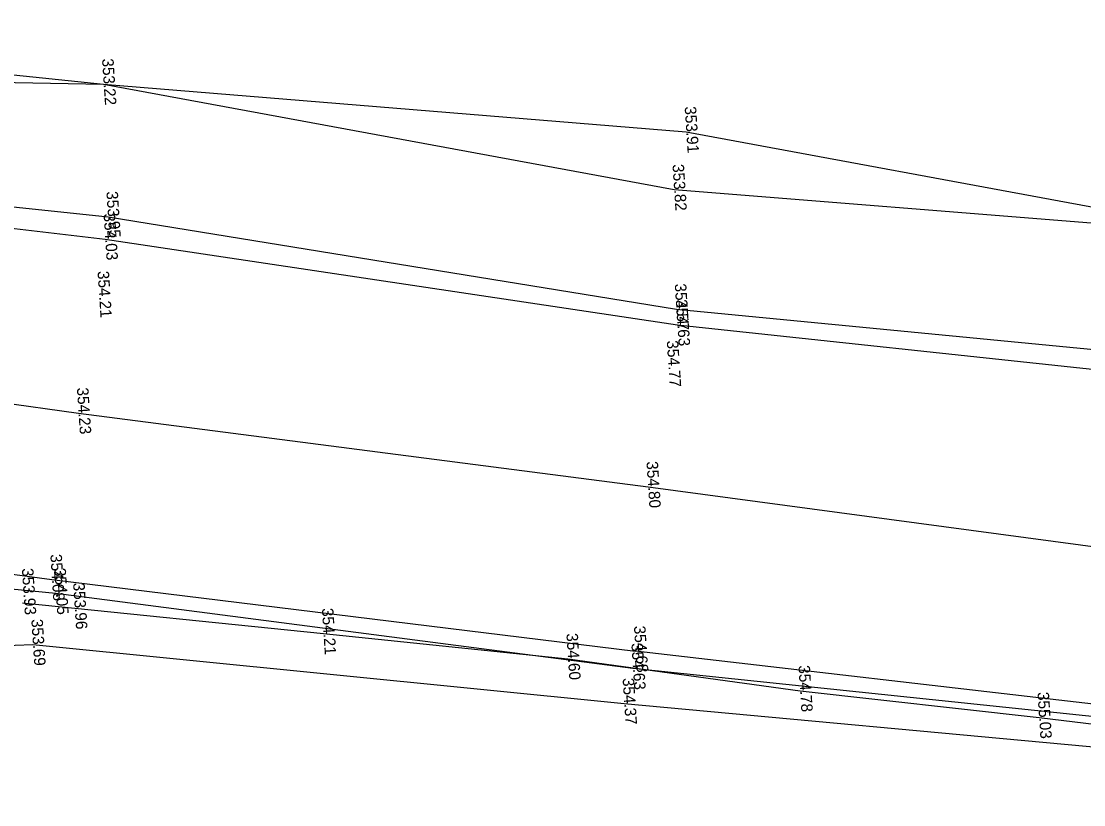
# Model space of a CAD drawing. Extents: x -600096 to -597522, y -1151695 to -1149849.
# Drawn here: x -599588.39 to -599571.03, y -1151436.31 to -1151423.5 of the extents above; entities that cross this region are included whole.
import ezdxf

# ---------------------------------------------------------------- set-up
doc = ezdxf.new("R2010")
doc.units = 0
for name, color, linetype in [('Hrana komunikace', 7, 'Continuous'), ('MPPV_Dno_prikopu', 7, 'Continuous'), ('MPPV_komunikace', 7, 'Continuous'), ('MPPV_svah', 7, 'Continuous'), ('MPPV_vodorovne_znaceni', 7, 'Continuous'), ('Svodidla', 7, 'Continuous'), ('Vrstva 12', 7, 'Continuous')]:
    doc.layers.add(name, color=color, linetype=linetype)

msp = doc.modelspace()

# ---------------------------------------------------------------- linework, layer by layer
at = {"layer": 'Hrana komunikace'}
for p, q in [((-599597.086, -1151425.633), (-599586.975, -1151426.697)), ((-599586.975, -1151426.697), (-599577.687, -1151428.205)), ((-599577.687, -1151428.205), (-599568.056, -1151429.139)), ((-599587.826, -1151432.855), (-599598.052, -1151431.869)), ((-599578.396, -1151434.083), (-599587.826, -1151432.855)), ((-599568.951, -1151435.07), (-599578.396, -1151434.083))]:
    msp.add_line(p, q, dxfattribs=at)
at = {"layer": 'MPPV_Dno_prikopu'}
for p, q in [((-599597.189, -1151424.357), (-599587.047, -1151424.527)), ((-599587.047, -1151424.527), (-599577.724, -1151426.253)), ((-599577.724, -1151426.253), (-599568.437, -1151426.99))]:
    msp.add_line(p, q, dxfattribs=at)
at = {"layer": 'MPPV_komunikace'}
for p, q in [((-599597.19, -1151425.88), (-599587.021, -1151427.06)), ((-599587.021, -1151427.06), (-599577.67, -1151428.464)), ((-599577.67, -1151428.464), (-599568.103, -1151429.483)), ((-599597.941, -1151431.261), (-599587.891, -1151432.629)), ((-599587.891, -1151432.629), (-599578.354, -1151433.8)), ((-599568.772, -1151434.908), (-599578.354, -1151433.8))]:
    msp.add_line(p, q, dxfattribs=at)
at = {"layer": 'MPPV_svah'}
for p, q in [((-599597.105, -1151423.5), (-599587.047, -1151424.527)), ((-599587.047, -1151424.527), (-599577.525, -1151425.308)), ((-599577.525, -1151425.308), (-599568.437, -1151426.99)), ((-599597.892, -1151434.013), (-599588.202, -1151433.691)), ((-599588.202, -1151433.691), (-599578.539, -1151434.654)), ((-599578.539, -1151434.654), (-599568.931, -1151435.54))]:
    msp.add_line(p, q, dxfattribs=at)
at = {"layer": 'MPPV_vodorovne_znaceni'}
for p, q in [((-599597.498, -1151428.536), (-599587.457, -1151429.905)), ((-599587.457, -1151429.905), (-599578.149, -1151431.111)), ((-599578.149, -1151431.111), (-599568.413, -1151432.42))]:
    msp.add_line(p, q, dxfattribs=at)
at = {"layer": 'Svodidla'}
for p, q in [((-599588.372, -1151433.008), (-599583.454, -1151433.512)), ((-599583.454, -1151433.512), (-599579.458, -1151433.922)), ((-599579.458, -1151433.922), (-599575.666, -1151434.446)), ((-599575.666, -1151434.446), (-599571.76, -1151434.883)), ((-599571.76, -1151434.883), (-599559.841, -1151436.31))]:
    msp.add_line(p, q, dxfattribs=at)

# ---------------------------------------------------------------- texts
at = {"layer": 'Vrstva 12'}
for s, p in [('353.22 ', (-599587.073, -1151424.114)), ('353.91 ', (-599577.552, -1151424.896)), ('353.82 ', (-599577.751, -1151425.841)), ('353.95 ', (-599587.002, -1151426.284)), ('354.03 ', (-599587.048, -1151426.648)), ('354.21 ', (-599587.147, -1151427.587)), ('354.57 ', (-599577.714, -1151427.793)), ('354.63 ', (-599577.697, -1151428.052)), ('354.77 ', (-599577.844, -1151428.723)), ('354.23 ', (-599587.484, -1151429.493)), ('354.80 ', (-599578.176, -1151430.699)), ('354.08 ', (-599587.918, -1151432.217)), ('353.93 ', (-599588.383, -1151432.447)), ('354.05 ', (-599587.853, -1151432.443)), ('353.96 ', (-599587.546, -1151432.683)), ('354.21 ', (-599583.481, -1151433.099)), ('353.69 ', (-599588.229, -1151433.279)), ('354.68 ', (-599578.381, -1151433.388)), ('354.60 ', (-599579.485, -1151433.51)), ('354.63 ', (-599578.423, -1151433.671)), ('354.78 ', (-599575.693, -1151434.034)), ('354.37 ', (-599578.566, -1151434.242)), ('355.03 ', (-599571.786, -1151434.471))]:
    msp.add_text(s, height=0.1875, rotation=273.7347, dxfattribs=at).set_placement(p)

doc.saveas('drawing.dxf')
